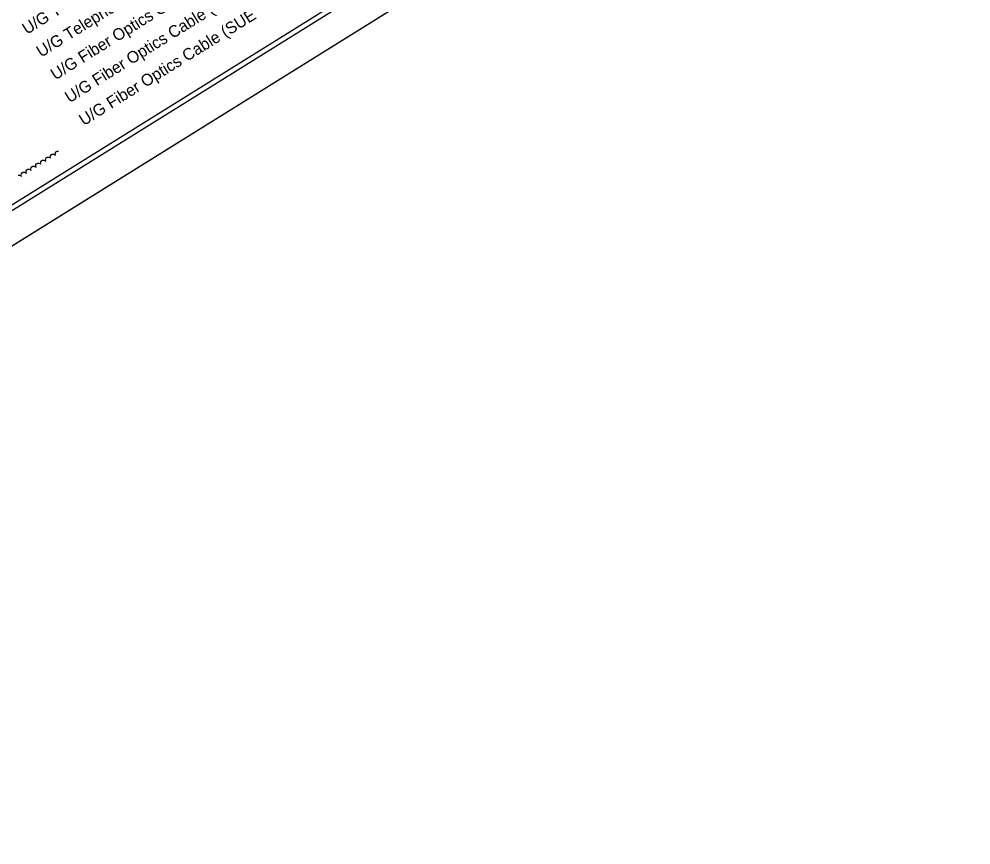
# Model space of a CAD drawing. Extents: x 2046091 to 2048102, y 759061 to 760885.
# Drawn here: x 2047393 to 2048102, y 759061 to 759676 of the extents above; entities that cross this region are included whole.
import ezdxf

# ---------------------------------------------------------------- set-up
doc = ezdxf.new("R2010")
doc.units = 0
for name, color, linetype in [('Sheet Cutting Line CELL', 7, 'Continuous'), ('Sheet Plot Border Inside CELL', 7, 'Continuous'), ('Sheet Plot Border Outside CELL', 7, 'Continuous'), ('Sheet Symbology CELL', 7, 'Continuous')]:
    doc.layers.add(name, color=color, linetype=linetype)

msp = doc.modelspace()

# ---------------------------------------------------------------- linework, layer by layer
at = {"layer": 'Sheet Cutting Line CELL'}
msp.add_line((2046672.2, 759061.26), (2048101.59, 759951.6), dxfattribs=at)
at = {"layer": 'Sheet Plot Border Inside CELL'}
msp.add_lwpolyline([(2046671.37, 759087.19), (2048085.9, 759968.28), (2047528.06, 760863.85), (2046113.53, 759982.76)], close=True, dxfattribs=at)
at = {"layer": 'Sheet Plot Border Outside CELL'}
msp.add_lwpolyline([(2046672.2, 759061.26), (2048101.59, 759951.6), (2047520.01, 760885.29), (2046090.62, 759994.95)], close=True, dxfattribs=at)
at = {"layer": 'Sheet Symbology CELL'}
for p, q in [((2047413.01, 759570.98), (2047413.18, 759571.85)), ((2047413.18, 759571.85), (2047413.62, 759572.66)), ((2047413.62, 759572.66), (2047414.42, 759573.16)), ((2047414.42, 759573.16), (2047415.37, 759573.16)), ((2047415.37, 759573.16), (2047416.18, 759572.9)), ((2047416.18, 759572.9), (2047416.8, 759572.28)), ((2047416.62, 759573.23), (2047416.78, 759574.1)), ((2047416.87, 759572.26), (2047416.62, 759573.23)), ((2047416.78, 759574.1), (2047417.23, 759574.9)), ((2047417.23, 759574.9), (2047418.03, 759575.41)), ((2047418.03, 759575.41), (2047418.98, 759575.4)), ((2047418.98, 759575.4), (2047419.79, 759575.14)), ((2047419.79, 759575.14), (2047420.41, 759574.53)), ((2047420.23, 759575.48), (2047420.39, 759576.34)), ((2047420.47, 759574.51), (2047420.23, 759575.48)), ((2047420.39, 759576.34), (2047420.83, 759577.15)), ((2047420.83, 759577.15), (2047421.64, 759577.65)), ((2047421.64, 759577.65), (2047422.58, 759577.65)), ((2047422.58, 759577.65), (2047422.65, 759577.63)), ((2047399.19, 759563.67), (2047400, 759564.17)), ((2047400, 759564.17), (2047400.94, 759564.17)), ((2047400.94, 759564.17), (2047401.75, 759563.91)), ((2047402.19, 759564.24), (2047402.36, 759565.11)), ((2047402.44, 759563.28), (2047402.19, 759564.24)), ((2047402.36, 759565.11), (2047402.8, 759565.91)), ((2047402.8, 759565.91), (2047403.6, 759566.42)), ((2047403.6, 759566.42), (2047404.55, 759566.42)), ((2047404.55, 759566.42), (2047405.36, 759566.15)), ((2047405.36, 759566.15), (2047405.98, 759565.54)), ((2047405.8, 759566.49), (2047405.96, 759567.36)), ((2047406.04, 759565.52), (2047405.8, 759566.49)), ((2047405.96, 759567.36), (2047406.4, 759568.16)), ((2047406.4, 759568.16), (2047407.21, 759568.66)), ((2047407.21, 759568.66), (2047408.15, 759568.66)), ((2047408.15, 759568.66), (2047408.96, 759568.4)), ((2047408.96, 759568.4), (2047409.58, 759567.79)), ((2047409.4, 759568.73), (2047409.57, 759569.6)), ((2047409.65, 759567.77), (2047409.4, 759568.73)), ((2047409.57, 759569.6), (2047410.01, 759570.41)), ((2047410.01, 759570.41), (2047410.82, 759570.91)), ((2047410.82, 759570.91), (2047411.76, 759570.91)), ((2047411.76, 759570.91), (2047412.57, 759570.65)), ((2047412.57, 759570.65), (2047413.19, 759570.03)), ((2047413.26, 759570.02), (2047413.01, 759570.98)), ((2047392.78, 759559.68), (2047393.72, 759559.67)), ((2047393.72, 759559.67), (2047394.53, 759559.41)), ((2047394.53, 759559.41), (2047395.15, 759558.8)), ((2047394.97, 759559.75), (2047395.14, 759560.62)), ((2047395.22, 759558.78), (2047394.97, 759559.75)), ((2047395.14, 759560.62), (2047395.58, 759561.42)), ((2047395.58, 759561.42), (2047396.39, 759561.92)), ((2047396.39, 759561.92), (2047397.33, 759561.92)), ((2047397.33, 759561.92), (2047398.14, 759561.66)), ((2047398.14, 759561.66), (2047398.76, 759561.04)), ((2047398.58, 759561.99), (2047398.75, 759562.86)), ((2047398.83, 759561.03), (2047398.58, 759561.99)), ((2047398.75, 759562.86), (2047399.19, 759563.67)), ((2047401.75, 759563.91), (2047402.37, 759563.29))]:
    msp.add_line(p, q, dxfattribs=at)
msp.add_lwpolyline([(2047518.8, 760855.08), (2046245.59, 760062.02), (2046800.2, 759171.64), (2048073.4, 759964.7)], close=True, dxfattribs=at)

# ---------------------------------------------------------------- texts
for s, p in [('U/G Telephone Conduit (SUE - LOS C)*', (2047399.15, 759664.06)), ('U/G Telephone Conduit (SUE - LOS D)*', (2047409.72, 759647.09)), ('U/G Fiber Optics Cable (SUE - LOS B)*', (2047420.29, 759630.11)), ('U/G Fiber Optics Cable (SUE - LOS C)*', (2047430.87, 759613.14)), ('U/G Fiber Optics Cable (SUE - LOS D)*', (2047441.44, 759596.16))]:
    msp.add_text(s, height=8.75, rotation=31.91803, dxfattribs=at).set_placement(p)

doc.saveas('drawing.dxf')
